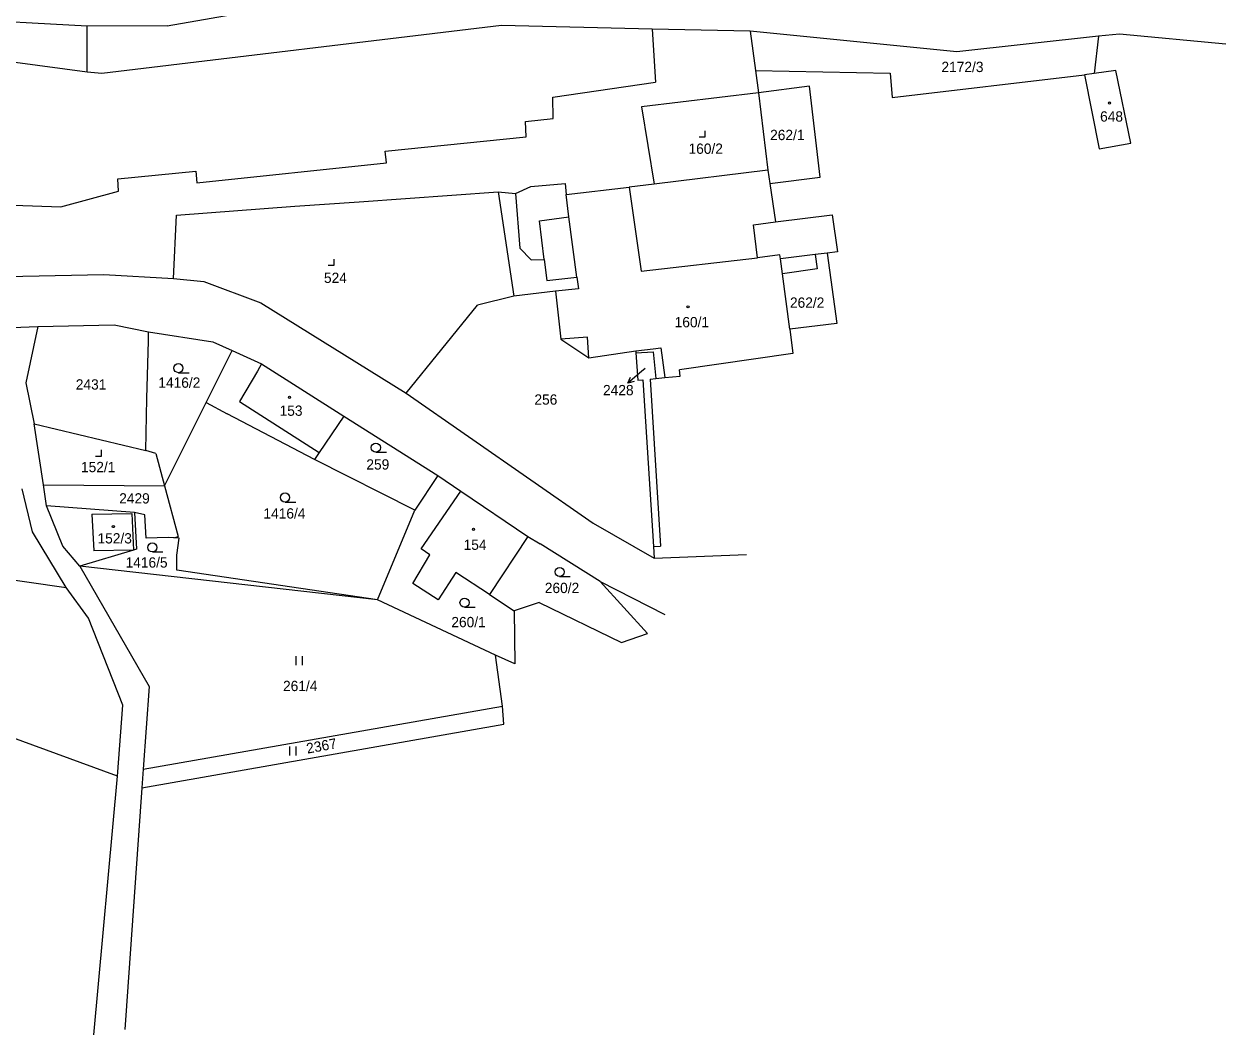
# Model space of a CAD drawing. Extents: x -717507 to -715515, y -957700 to -954941.
# Drawn here: x -716853.4 to -716654.6, y -957588.9 to -957421.8 of the extents above; entities that cross this region are included whole.
import ezdxf

# ---------------------------------------------------------------- set-up
doc = ezdxf.new("R2010")
doc.units = 0
for name, color, linetype in [('Hranice parcel', 7, 'Continuous'), ('Parcelní čísla', 7, 'Continuous'), ('Pop  PČ popisy', 7, 'Continuous'), ('Vnitřní kresba', 7, 'Continuous'), ('Značky budov', 7, 'Continuous'), ('Značky kultur', 7, 'Continuous')]:
    doc.layers.add(name, color=color, linetype=linetype)

msp = doc.modelspace()

# ---------------------------------------------------------------- linework, layer by layer
at = {"layer": 'Hranice parcel'}
for points in [[(-716829.71, -957422.08), (-716806.59, -957418.02)], [(-716842.94, -957422.09), (-716865.2, -957420.88)], [(-716829.71, -957422.08), (-716842.94, -957422.09)], [(-716774.39, -957422.02), (-716840.49, -957429.94)], [(-716749.47, -957422.61), (-716774.39, -957422.02)], [(-716733.27, -957422.95), (-716749.47, -957422.61)], [(-716733.27, -957422.95), (-716732.39, -957429.42)], [(-716699.06, -957426.35), (-716733.27, -957422.95)], [(-716672.16, -957423.44), (-716675.61, -957423.78)], [(-716654.55, -957425.08), (-716672.16, -957423.44)], [(-716675.61, -957423.78), (-716699.06, -957426.35)], [(-716675.61, -957423.78), (-716676.37, -957429.92)], [(-716842.94, -957429.74), (-716863.09, -957426.99)], [(-716732.39, -957429.42), (-716731.9, -957433.14)], [(-716732.39, -957429.42), (-716710.08, -957429.87)], [(-716672.75, -957429.44), (-716676.37, -957429.92)], [(-716670.27, -957441.47), (-716672.75, -957429.44)], [(-716840.49, -957429.94), (-716842.94, -957429.74)], [(-716710.08, -957429.87), (-716709.77, -957433.9)], [(-716709.77, -957433.9), (-716677.97, -957430.16)], [(-716676.37, -957429.92), (-716677.97, -957430.16)], [(-716677.97, -957430.16), (-716675.52, -957442.41)], [(-716731.9, -957433.14), (-716751.21, -957435.43)], [(-716723.41, -957432.04), (-716731.9, -957433.14)], [(-716731.9, -957433.14), (-716730.31, -957445.93)], [(-716721.65, -957447.06), (-716723.41, -957432.04)], [(-716751.21, -957435.43), (-716749.11, -957448.25)], [(-716675.52, -957442.41), (-716670.27, -957441.47)], [(-716730.31, -957445.93), (-716749.11, -957448.25)], [(-716730.31, -957445.93), (-716729.99, -957448.13)], [(-716729.99, -957448.13), (-716721.65, -957447.06)], [(-716772.06, -957449.76), (-716769.53, -957448.63)], [(-716769.53, -957448.63), (-716763.85, -957448.11)], [(-716763.85, -957448.11), (-716763.67, -957449.97)], [(-716763.67, -957449.97), (-716753.29, -957448.75)], [(-716749.11, -957448.25), (-716753.29, -957448.75)], [(-716729.99, -957448.13), (-716729.08, -957454.46)], [(-716808.58, -957451.87), (-716797.95, -957451.14)], [(-716797.95, -957451.14), (-716774.92, -957449.48)], [(-716774.92, -957449.48), (-716772.06, -957449.76)], [(-716774.92, -957449.48), (-716772.33, -957466.76)], [(-716828.17, -957453.34), (-716808.58, -957451.87)], [(-716729.08, -957454.46), (-716719.71, -957453.3)], [(-716719.71, -957453.3), (-716718.82, -957459.4)], [(-716828.65, -957463.84), (-716828.17, -957453.34)], [(-716720.49, -957459.62), (-716722.5, -957459.89)], [(-716722.5, -957459.89), (-716722.18, -957462.21)], [(-716718.82, -957459.4), (-716720.49, -957459.62)], [(-716720.49, -957459.62), (-716718.91, -957471.28)], [(-716869.66, -957463.78), (-716840.19, -957463.17)], [(-716840.19, -957463.17), (-716828.65, -957463.84)], [(-716722.18, -957462.21), (-716727.92, -957463.04)], [(-716726.7, -957472.19), (-716727.92, -957463.04)], [(-716828.65, -957463.84), (-716823.61, -957464.32)], [(-716823.61, -957464.32), (-716814.21, -957467.86)], [(-716772.33, -957466.76), (-716778.33, -957468.22)], [(-716765.44, -957465.93), (-716772.33, -957466.76)], [(-716765.44, -957465.93), (-716764.55, -957473.84)], [(-716814.21, -957467.86), (-716790.17, -957482.82)], [(-716790.17, -957482.82), (-716778.33, -957468.22)], [(-716855.35, -957471.94), (-716851.08, -957471.79)], [(-716851.08, -957471.79), (-716853.06, -957481.11)], [(-716851.08, -957471.79), (-716838.45, -957471.52)], [(-716838.45, -957471.52), (-716832.8, -957472.68)], [(-716832.8, -957472.68), (-716822.11, -957474.31)], [(-716832.79, -957474.14), (-716832.8, -957472.68)], [(-716718.91, -957471.28), (-716726.7, -957472.19)], [(-716726.7, -957472.19), (-716726.17, -957476.25)], [(-716833.06, -957483.7), (-716832.79, -957474.14)], [(-716822.11, -957474.31), (-716818.91, -957475.75)], [(-716764.55, -957473.84), (-716759.94, -957476.93)], [(-716823.22, -957484.36), (-716818.91, -957475.75)], [(-716818.91, -957475.75), (-716814.06, -957477.93)], [(-716759.94, -957476.93), (-716752.17, -957475.82)], [(-716752.17, -957475.82), (-716752.15, -957476.14)], [(-716752.15, -957476.14), (-716749.27, -957475.97)], [(-716752.15, -957476.14), (-716751.85, -957480.63)], [(-716749.27, -957475.97), (-716748.87, -957480.38)], [(-716726.17, -957476.25), (-716744.92, -957478.94)], [(-716814.77, -957479.16), (-716817.71, -957484.18)], [(-716814.06, -957477.93), (-716814.77, -957479.16)], [(-716814.06, -957477.93), (-716800.45, -957486.6)], [(-716744.81, -957479.97), (-716744.92, -957478.94)], [(-716853.06, -957481.11), (-716851.69, -957487.87)], [(-716751.85, -957480.63), (-716751.02, -957480.58)], [(-716751.02, -957480.58), (-716749.23, -957508.14)], [(-716749.79, -957480.46), (-716748.87, -957480.38)], [(-716749.79, -957480.46), (-716748.11, -957508.07)], [(-716748.87, -957480.38), (-716747.37, -957480.22)], [(-716747.37, -957480.22), (-716744.81, -957479.97)], [(-716790.17, -957482.82), (-716759.23, -957504.28)], [(-716833.24, -957492.27), (-716833.06, -957483.7)], [(-716830.11, -957498.14), (-716823.22, -957484.36)], [(-716823.22, -957484.36), (-716819.75, -957486.23)], [(-716817.71, -957484.18), (-716804.54, -957492.61)], [(-716805.33, -957493.77), (-716819.75, -957486.23)], [(-716800.45, -957486.6), (-716804.54, -957492.61)], [(-716800.45, -957486.6), (-716784.93, -957496.43)], [(-716850.16, -957497.95), (-716851.69, -957487.87)], [(-716851.69, -957487.87), (-716833.24, -957492.27)], [(-716831.56, -957492.75), (-716833.24, -957492.27)], [(-716831.56, -957492.75), (-716830.11, -957498.14)], [(-716788.72, -957502.16), (-716805.33, -957493.77)], [(-716784.93, -957496.43), (-716788.72, -957502.16)], [(-716784.93, -957496.43), (-716781.13, -957499.01)], [(-716851.97, -957505.73), (-716853.66, -957498.59)], [(-716850.16, -957497.95), (-716830.11, -957498.14)], [(-716849.63, -957501.43), (-716850.16, -957497.95)], [(-716830.11, -957498.14), (-716827.86, -957506.5)], [(-716787.65, -957508.53), (-716781.13, -957499.01)], [(-716781.13, -957499.01), (-716770.05, -957506.48)], [(-716846.95, -957508.12), (-716849.63, -957501.43)], [(-716835.08, -957502.51), (-716849.63, -957501.43)], [(-716833.38, -957502.93), (-716835.08, -957502.51)], [(-716835.08, -957502.51), (-716834.74, -957508.58)], [(-716833.17, -957506.79), (-716833.38, -957502.93)], [(-716794.89, -957516.95), (-716788.72, -957502.16)], [(-716759.23, -957504.28), (-716749.12, -957510.1)], [(-716846.4, -957514.94), (-716851.97, -957505.73)], [(-716829.51, -957506.67), (-716833.17, -957506.79)], [(-716828.57, -957506.72), (-716829.51, -957506.67)], [(-716828.57, -957506.72), (-716827.86, -957506.5)], [(-716827.7, -957506.76), (-716828.57, -957506.72)], [(-716828.1, -957509.61), (-716827.7, -957506.76)], [(-716770.05, -957506.48), (-716776.36, -957516.08)], [(-716770.05, -957506.48), (-716767.97, -957507.73)], [(-716844.14, -957511.4), (-716846.95, -957508.12)], [(-716835.27, -957508.73), (-716844.14, -957511.4)], [(-716834.74, -957508.58), (-716835.27, -957508.73)], [(-716786.22, -957509.52), (-716787.65, -957508.53)], [(-716758.05, -957513.94), (-716767.97, -957507.73)], [(-716749.23, -957508.14), (-716748.11, -957508.07)], [(-716749.23, -957508.14), (-716749.12, -957510.1)], [(-716884.3, -957509.46), (-716846.4, -957514.94)], [(-716828.08, -957512.06), (-716828.1, -957509.61)], [(-716789.05, -957514.27), (-716786.22, -957509.52)], [(-716749.12, -957510.1), (-716733.84, -957509.47)], [(-716844.14, -957511.4), (-716832.69, -957531.31)], [(-716794.89, -957516.95), (-716844.14, -957511.4)], [(-716794.89, -957516.95), (-716828.08, -957512.06)], [(-716781.92, -957512.43), (-716784.85, -957516.97)], [(-716776.36, -957516.08), (-716781.92, -957512.43)], [(-716842.7, -957520), (-716846.4, -957514.94)], [(-716784.85, -957516.97), (-716789.05, -957514.27)], [(-716758.05, -957513.94), (-716747.35, -957519.4)], [(-716750.24, -957522.55), (-716758.05, -957513.94)], [(-716775.38, -957526.12), (-716794.89, -957516.95)], [(-716776.36, -957516.08), (-716772.3, -957518.81)], [(-716768.13, -957517.41), (-716772.3, -957518.81)], [(-716772.3, -957518.81), (-716772.16, -957527.57)], [(-716768.13, -957517.41), (-716754.55, -957524.05)], [(-716837.04, -957534.39), (-716842.7, -957520)], [(-716754.55, -957524.05), (-716750.24, -957522.55)], [(-716837.89, -957546.13), (-716893.37, -957525.87)], [(-716774.24, -957534.55), (-716775.38, -957526.12)], [(-716772.16, -957527.57), (-716775.38, -957526.12)], [(-716832.69, -957531.31), (-716833.66, -957544.97)], [(-716837.89, -957546.13), (-716837.04, -957534.39)], [(-716833.66, -957544.97), (-716774.24, -957534.55)], [(-716774, -957537.55), (-716774.24, -957534.55)], [(-716833.87, -957548.04), (-716774, -957537.55)], [(-716841.81, -957588.92), (-716837.89, -957546.13)], [(-716833.66, -957544.97), (-716833.87, -957548.04)], [(-716833.87, -957548.04), (-716836.7, -957588.04)]]:
    msp.add_lwpolyline(points, dxfattribs=at)
at = {"layer": 'Pop  PČ popisy'}
for points in [[(-716750.6, -957478.73), (-716751.21, -957479.23)], [(-716751.21, -957479.23), (-716753.51, -957481.15)], [(-716752.43, -957480.89), (-716753.51, -957481.15), (-716753.07, -957480.13)]]:
    msp.add_lwpolyline(points, dxfattribs=at)
at = {"layer": 'Vnitřní kresba'}
for points in [[(-716842.94, -957429.74), (-716842.94, -957422.09)], [(-716749.47, -957422.61), (-716748.89, -957431.37)], [(-716765.92, -957433.87), (-716748.89, -957431.37)], [(-716765.86, -957437.39), (-716765.92, -957433.87)], [(-716770.43, -957437.86), (-716765.86, -957437.39)], [(-716770.28, -957440.41), (-716770.43, -957437.86)], [(-716793.64, -957442.78), (-716770.28, -957440.41)], [(-716793.43, -957444.69), (-716793.64, -957442.78)], [(-716824.76, -957448.04), (-716793.43, -957444.69)], [(-716837.83, -957447.33), (-716824.94, -957446.06)], [(-716837.76, -957449.38), (-716837.83, -957447.33)], [(-716824.94, -957446.06), (-716824.76, -957448.04)], [(-716753.29, -957448.75), (-716751.28, -957462.64)], [(-716898.99, -957450.17), (-716847.25, -957451.97)], [(-716847.25, -957451.97), (-716837.76, -957449.38)], [(-716772.06, -957449.76), (-716771.36, -957458.82)], [(-716763.24, -957453.66), (-716763.67, -957449.97)], [(-716768.09, -957454.3), (-716763.24, -957453.66)], [(-716767.33, -957460.71), (-716768.09, -957454.3)], [(-716761.9, -957463.61), (-716763.24, -957453.66)], [(-716732.68, -957454.95), (-716729.08, -957454.46)], [(-716732.04, -957460.44), (-716732.68, -957454.95)], [(-716771.36, -957458.82), (-716769.47, -957460.77)], [(-716769.47, -957460.77), (-716767.33, -957460.71)], [(-716767.33, -957460.71), (-716766.9, -957464.16)], [(-716751.28, -957462.64), (-716732.04, -957460.44)], [(-716728.34, -957459.92), (-716732.04, -957460.44)], [(-716728.26, -957460.58), (-716728.34, -957459.92)], [(-716722.5, -957459.89), (-716728.26, -957460.58)], [(-716727.92, -957463.04), (-716728.26, -957460.58)], [(-716766.9, -957464.16), (-716761.9, -957463.61)], [(-716761.9, -957463.61), (-716761.62, -957465.54)], [(-716761.62, -957465.54), (-716765.44, -957465.93)], [(-716760.15, -957473.51), (-716764.55, -957473.84)], [(-716759.94, -957476.93), (-716760.15, -957473.51)], [(-716752.17, -957475.82), (-716749.3, -957475.44)], [(-716749.3, -957475.44), (-716748.04, -957475.29)], [(-716748.04, -957475.29), (-716747.37, -957480.22)], [(-716804.54, -957492.61), (-716805.33, -957493.77)], [(-716842.16, -957502.82), (-716835.54, -957502.68)], [(-716842.16, -957502.82), (-716841.84, -957508.86)], [(-716835.54, -957502.68), (-716835.27, -957508.73)], [(-716835.27, -957508.73), (-716841.84, -957508.86)]]:
    msp.add_lwpolyline(points, dxfattribs=at)
at = {"layer": 'Značky budov'}
for centre in [(-716673.8, -957434.82), (-716743.53, -957468.52), (-716809.44, -957483.48), (-716838.59, -957504.86), (-716779.01, -957505.31)]:
    msp.add_circle(centre, 0.175, dxfattribs=at)
at = {"layer": 'Značky kultur'}
for points in [[(-716741.71, -957440.42), (-716740.71, -957440.42), (-716740.71, -957439.42)], [(-716803.06, -957461.65), (-716802.06, -957461.65), (-716802.06, -957460.65)], [(-716827.82, -957479.41), (-716826.07, -957479.41)], [(-716841.56, -957493.19), (-716840.56, -957493.19), (-716840.56, -957492.19)], [(-716795.17, -957492.55), (-716793.42, -957492.55)], [(-716810.18, -957500.8), (-716808.43, -957500.8)], [(-716832.14, -957509.06), (-716830.39, -957509.06)], [(-716764.77, -957513.11), (-716763.02, -957513.11)], [(-716780.5, -957518.18), (-716778.75, -957518.18)], [(-716808.35, -957527.79), (-716808.35, -957526.29)], [(-716807.31, -957527.79), (-716807.31, -957526.29)], [(-716809.41, -957542.71), (-716809.41, -957541.21)], [(-716808.37, -957542.71), (-716808.37, -957541.21)]]:
    msp.add_lwpolyline(points, dxfattribs=at)
for centre in [(-716827.82, -957478.66), (-716795.17, -957491.8), (-716810.18, -957500.05), (-716832.14, -957508.31), (-716764.77, -957512.36), (-716780.5, -957517.43)]:
    msp.add_circle(centre, 0.75, dxfattribs=at)

# ---------------------------------------------------------------- texts
at = {"layer": 'Parcelní čísla'}
for s, p in [('2172/3', (-716701.61, -957429.7)), ('648', (-716675.37, -957437.89)), ('262/1', (-716729.95, -957440.95)), ('160/2', (-716743.45, -957443.22)), ('524', (-716803.75, -957464.57)), ('262/2', (-716726.67, -957468.67)), ('160/1', (-716745.74, -957471.9)), ('2431', (-716844.8, -957482.2)), ('1416/2', (-716831.15, -957481.9)), ('256', (-716768.94, -957484.7)), ('2428', (-716757.59, -957483.14)), ('153', (-716811.09, -957486.54)), ('152/1', (-716843.94, -957495.86)), ('259', (-716796.74, -957495.43)), ('2429', (-716837.62, -957501.04)), ('1416/4', (-716813.76, -957503.53)), ('152/3', (-716841.21, -957507.65)), ('154', (-716780.65, -957508.71)), ('1416/5', (-716836.57, -957511.64)), ('260/2', (-716767.22, -957515.85)), ('260/1', (-716782.68, -957521.5)), ('261/4', (-716810.52, -957532.06))]:
    msp.add_text(s, height=1.7, dxfattribs=at).set_placement(p)
msp.add_text('2367', height=1.7, rotation=10.3001, dxfattribs=at).set_placement((-716806.49, -957542.41))

doc.saveas('drawing.dxf')
